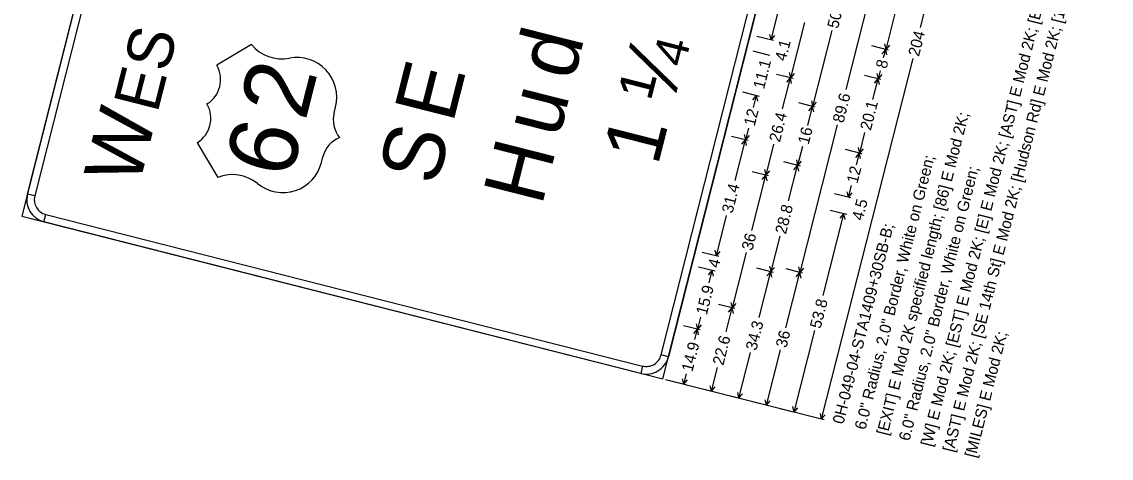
# Model space of a CAD drawing. Extents: x 670002 to 670131, y 737835 to 738002.
# Drawn here: x 670004.98 to 670052.75, y 737849.22 to 737868.34 of the extents above; entities that cross this region are included whole.
import ezdxf

# ---------------------------------------------------------------- set-up
doc = ezdxf.new("R2010")
doc.units = 0
doc.layers.add('R_SIGN', color=7, linetype='Continuous')

msp = doc.modelspace()

# ---------------------------------------------------------------- linework, layer by layer
at = {"layer": 'R_SIGN'}
for p, q in [((670013.338, 737892.779), (670004.98, 737859.823)), ((670033.09, 737852.693), (670041.448, 737885.65)), ((670044.389, 737868.084), (670048.397, 737883.887)), ((670041.129, 737865.372), (670042.768, 737871.835)), ((670043.727, 737870.547), (670042.861, 737867.131)), ((670038.329, 737869.546), (670037.821, 737867.544)), ((670039.301, 737868.309), (670038.686, 737865.882)), ((670037.942, 737867.514), (670037.217, 737867.697)), ((670037.768, 737867.788), (670037.821, 737867.544)), ((670037.984, 737867.733), (670037.821, 737867.544)), ((670040.498, 737867.956), (670039.655, 737864.632)), ((670015.05, 737867.341), (670013.531, 737866.437)), ((670037.778, 737866.867), (670037.053, 737867.051)), ((670042.982, 737867.1), (670042.257, 737867.284)), ((670042.698, 737866.942), (670042.861, 737867.131)), ((670042.77, 737866.772), (670042.861, 737867.131)), ((670042.808, 737867.374), (670042.861, 737867.131)), ((670043.024, 737867.32), (670042.861, 737867.131)), ((670042.914, 737866.887), (670042.861, 737867.131)), ((670044.046, 737866.734), (670040.038, 737850.931)), ((670038.632, 737866.126), (670038.686, 737865.882)), ((670042.624, 737866.197), (670042.533, 737865.838)), ((670038.806, 737865.852), (670038.081, 737866.036)), ((670038.341, 737864.524), (670038.686, 737865.882)), ((670038.523, 737865.694), (670038.686, 737865.882)), ((670038.849, 737866.071), (670038.686, 737865.882)), ((670038.739, 737865.639), (670038.686, 737865.882)), ((670042.654, 737865.808), (670041.929, 737865.992)), ((670042.305, 737864.94), (670042.533, 737865.838)), ((670042.37, 737865.65), (670042.533, 737865.838)), ((670042.48, 737866.082), (670042.533, 737865.838)), ((670042.696, 737866.027), (670042.533, 737865.838)), ((670042.586, 737865.595), (670042.533, 737865.838)), ((670037.323, 737865.074), (670036.598, 737865.258)), ((670037.039, 737864.916), (670037.202, 737865.105)), ((670037.072, 737864.59), (670037.202, 737865.105)), ((670037.255, 737864.861), (670037.202, 737865.105)), ((670039.776, 737864.602), (670039.051, 737864.786)), ((670039.602, 737864.876), (670039.655, 737864.632)), ((670039.818, 737864.821), (670039.655, 737864.632)), ((670018.677, 737864.358), (670018.739, 737864.6)), ((670039.444, 737863.8), (670039.655, 737864.632)), ((670039.492, 737864.444), (670039.655, 737864.632)), ((670039.708, 737864.389), (670039.655, 737864.632)), ((670040.735, 737863.822), (670039.096, 737857.36)), ((670036.831, 737863.135), (670036.106, 737863.319)), ((670036.657, 737863.41), (670036.711, 737863.166)), ((670036.841, 737863.681), (670036.711, 737863.166)), ((670036.873, 737863.355), (670036.711, 737863.166)), ((670041.937, 737863.489), (670041.709, 737862.591)), ((670012.67, 737863.044), (670013.575, 737861.525)), ((670036.261, 737861.394), (670036.711, 737863.166)), ((670036.548, 737862.977), (670036.711, 737863.166)), ((670036.764, 737862.923), (670036.711, 737863.166)), ((670037.949, 737862.979), (670037.605, 737861.621)), ((670039.21, 737862.88), (670038.999, 737862.047)), ((670041.83, 737862.561), (670041.105, 737862.744)), ((670041.656, 737862.835), (670041.709, 737862.591)), ((670041.872, 737862.78), (670041.709, 737862.591)), ((670018.124, 737862.177), (670018.186, 737862.419)), ((670038.946, 737862.291), (670038.999, 737862.047)), ((670041.547, 737862.402), (670041.709, 737862.591)), ((670041.579, 737862.077), (670041.709, 737862.591)), ((670041.763, 737862.348), (670041.709, 737862.591)), ((670037.551, 737861.864), (670037.605, 737861.621)), ((670037.768, 737861.809), (670037.605, 737861.621)), ((670039.12, 737862.017), (670038.395, 737862.201)), ((670038.606, 737860.496), (670038.999, 737862.047)), ((670038.836, 737861.859), (670038.999, 737862.047)), ((670039.162, 737862.236), (670038.999, 737862.047)), ((670039.052, 737861.804), (670038.999, 737862.047)), ((670036.989, 737859.194), (670037.605, 737861.621)), ((670037.726, 737861.59), (670037.001, 737861.774)), ((670037.442, 737861.432), (670037.605, 737861.621)), ((670037.658, 737861.377), (670037.605, 737861.621)), ((670041.165, 737860.896), (670041.218, 737860.653)), ((670041.348, 737861.167), (670041.218, 737860.653)), ((670041.381, 737860.841), (670041.218, 737860.653)), ((670005.549, 737860.71), (670005.226, 737860.792)), ((670041.339, 737860.622), (670040.614, 737860.806)), ((670005.949, 737859.577), (670006.031, 737859.9)), ((670040.127, 737856.353), (670041.033, 737859.926)), ((670041.154, 737859.895), (670040.429, 737860.079)), ((670040.871, 737859.737), (670041.033, 737859.926)), ((670041.087, 737859.682), (670041.033, 737859.926)), ((670004.98, 737859.823), (670033.09, 737852.693)), ((670035.872, 737859.859), (670035.422, 737858.087)), ((670038.213, 737858.946), (670037.819, 737857.395)), ((670035.543, 737858.056), (670034.818, 737858.24)), ((670035.369, 737858.331), (670035.422, 737858.087)), ((670035.585, 737858.276), (670035.422, 737858.087)), ((670036.745, 737858.231), (670036.13, 737855.805)), ((670035.379, 737857.41), (670034.654, 737857.594)), ((670037.94, 737857.364), (670037.215, 737857.548)), ((670037.766, 737857.638), (670037.819, 737857.395)), ((670037.982, 737857.584), (670037.819, 737857.395)), ((670039.217, 737857.329), (670038.492, 737857.513)), ((670039.043, 737857.603), (670039.096, 737857.36)), ((670039.259, 737857.548), (670039.096, 737857.36)), ((670035.096, 737857.252), (670035.258, 737857.441)), ((670035.123, 737856.905), (670035.258, 737857.441)), ((670035.312, 737857.197), (670035.258, 737857.441)), ((670037.311, 737855.393), (670037.819, 737857.395)), ((670037.656, 737857.206), (670037.819, 737857.395)), ((670037.872, 737857.151), (670037.819, 737857.395)), ((670038.481, 737854.933), (670039.096, 737857.36)), ((670038.934, 737857.171), (670039.096, 737857.36)), ((670039.15, 737857.116), (670039.096, 737857.36)), ((670036.251, 737855.774), (670035.525, 737855.958)), ((670035.864, 737854.758), (670036.13, 737855.805)), ((670035.967, 737855.616), (670036.13, 737855.805)), ((670036.076, 737856.048), (670036.13, 737855.805)), ((670036.293, 737855.993), (670036.13, 737855.805)), ((670036.183, 737855.561), (670036.13, 737855.805)), ((670034.554, 737855.116), (670034.607, 737854.872)), ((670034.743, 737855.408), (670034.607, 737854.872)), ((670034.728, 737854.841), (670034.003, 737855.025)), ((670034.444, 737854.683), (670034.607, 737854.872)), ((670034.491, 737854.416), (670034.607, 737854.872)), ((670034.77, 737855.061), (670034.607, 737854.872)), ((670034.66, 737854.628), (670034.607, 737854.872)), ((670039.736, 737854.81), (670038.83, 737851.237)), ((670033.336, 737853.663), (670033.012, 737853.744)), ((670036.921, 737853.853), (670036.413, 737851.85)), ((670038.237, 737853.97), (670037.621, 737851.544)), ((670032.202, 737853.262), (670032.12, 737852.939)), ((670035.47, 737853.203), (670035.205, 737852.157)), ((670034.112, 737852.919), (670033.996, 737852.463)), ((670033.09, 737852.693), (670033.09, 737852.693)), ((670040.159, 737850.9), (670033.211, 737852.663)), ((670034.117, 737852.433), (670033.392, 737852.617)), ((670033.943, 737852.707), (670033.996, 737852.463)), ((670034.159, 737852.652), (670033.996, 737852.463)), ((670035.325, 737852.126), (670034.6, 737852.31)), ((670035.151, 737852.4), (670035.205, 737852.157)), ((670035.367, 737852.346), (670035.205, 737852.157)), ((670036.534, 737851.82), (670035.809, 737852.004)), ((670036.36, 737852.094), (670036.413, 737851.85)), ((670036.576, 737852.039), (670036.413, 737851.85)), ((670037.568, 737851.787), (670037.621, 737851.544)), ((670037.742, 737851.513), (670037.017, 737851.697)), ((670037.784, 737851.733), (670037.621, 737851.544)), ((670038.951, 737851.207), (670038.226, 737851.391)), ((670038.777, 737851.481), (670038.83, 737851.237)), ((670038.993, 737851.426), (670038.83, 737851.237)), ((670039.985, 737851.174), (670040.038, 737850.931)), ((670040.201, 737851.12), (670040.038, 737850.931))]:
    msp.add_line(p, q, dxfattribs=at)
for points in [[(670013.416, 737891.728), (670005.549, 737860.71), (670005.226, 737860.792), (670013.092, 737891.81), (670013.416, 737891.728)], [(670033.012, 737853.744), (670040.879, 737884.762), (670041.202, 737884.68), (670033.336, 737853.663), (670033.012, 737853.744)], [(670006.031, 737859.9), (670032.202, 737853.262), (670032.12, 737852.939), (670005.949, 737859.577), (670006.031, 737859.9)]]:
    msp.add_lwpolyline(points, close=True, dxfattribs=at)
for centre, radius, start, end in [((670016.388, 737868.468), 1.75, 220.1058, 280.7786), ((670017.043, 737865.03), 1.75, 345.7686, 100.779), ((670012.45, 737865.808), 1.25, 301.3415, 30.1958), ((670012.02, 737864.112), 1.25, 301.3415, 30.1958), ((670019.889, 737864.05), 1.25, 165.7688, 218.8986), ((670019.397, 737862.112), 1.25, 112.6384, 165.7688), ((670016.428, 737862.607), 1.75, 230.7582, 345.7686), ((670014.214, 737859.896), 1.75, 50.7581, 111.4314), ((670006.195, 737860.546), 1, 165.7688, 255.7684), ((670006.195, 737860.546), 0.667, 165.7688, 255.7684), ((670032.366, 737853.908), 0.667, 255.7684, 345.7686), ((670032.366, 737853.908), 1, 255.7684, 345.7686)]:
    msp.add_arc(centre, radius, start, end, dxfattribs=at)

# ---------------------------------------------------------------- texts
for s, height, p in [('[AST] E Mod 2K; [SE 14th St] E Mod 2K; [Hudson Rd] E Mod 2K; [1] E Mod 2K; [¼] E Mod 2K; ', 0.49869, (670045.839, 737849.46)), ('[W] E Mod 2K; [EST] E Mod 2K; [E] E Mod 2K; [AST] E Mod 2K; [E] E Mod 2K; ', 0.49869, (670044.872, 737849.705)), ('50.1', 0.4987, (670040.77, 737868.015)), ('S', 2, (670011.378, 737866.083)), ('d', 2.667, (670029.165, 737865.711)), ('¼', 2.5, (670033.542, 737864.663)), ('204', 0.4987, (670044.319, 737866.794)), ('4.1', 0.4987, (670038.479, 737866.589)), ('E', 2.667, (670023.878, 737863.847)), ('11.1', 0.4987, (670037.525, 737865.362)), ('8', 0.499, (670042.896, 737866.256)), ('E', 2, (670010.925, 737864.3)), ('2', 3, (670017.415, 737863.956)), ('u', 2.667, (670028.529, 737863.204)), ('89.6', 0.4987, (670041.008, 737863.882)), ('W', 2.5, (670010.11, 737861.085)), ('20.1', 0.4987, (670042.21, 737863.549)), ('12', 0.4987, (670037.113, 737863.74)), ('26.4', 0.4987, (670038.222, 737863.038)), ('[EXIT] E Mod 2K specified length; [86] E Mod 2K; ', 0.49869, (670042.939, 737850.195)), ('6', 3, (670016.766, 737861.397)), ('S', 2.667, (670023.183, 737861.107)), ('1', 2.5, (670032.866, 737861.997)), ('16', 0.4987, (670039.483, 737862.94)), ('H', 2.667, (670027.776, 737860.231)), ('6.0" Radius, 2.0" Border, White on Green; ', 0.49869, (670041.972, 737850.44)), ('12', 0.4987, (670041.621, 737861.227)), ('6.0" Radius, 2.0" Border, White on Green; ', 0.49869, (670043.905, 737849.95)), ('31.4', 0.4987, (670036.144, 737859.919)), ('4.5', 0.4987, (670041.853, 737859.608)), ('28.8', 0.4987, (670038.485, 737859.006)), ('0H-049-04-STA1409+30SB-B; ', 0.49869, (670041.005, 737850.686)), ('36', 0.4987, (670037.017, 737858.291)), ('4', 0.499, (670035.538, 737857.529)), ('15.9', 0.4987, (670035.015, 737855.467)), ('53.8', 0.4987, (670040.008, 737854.87)), ('34.3', 0.4987, (670037.193, 737853.912)), ('36', 0.4987, (670038.509, 737854.03)), ('[MILES] E Mod 2K; ', 0.49869, (670046.806, 737849.215)), ('14.9', 0.4987, (670034.384, 737852.979)), ('22.6', 0.4987, (670035.742, 737853.263))]:
    msp.add_text(s, height=height, rotation=75.7686, dxfattribs=at).set_placement(p)

doc.saveas('drawing.dxf')
